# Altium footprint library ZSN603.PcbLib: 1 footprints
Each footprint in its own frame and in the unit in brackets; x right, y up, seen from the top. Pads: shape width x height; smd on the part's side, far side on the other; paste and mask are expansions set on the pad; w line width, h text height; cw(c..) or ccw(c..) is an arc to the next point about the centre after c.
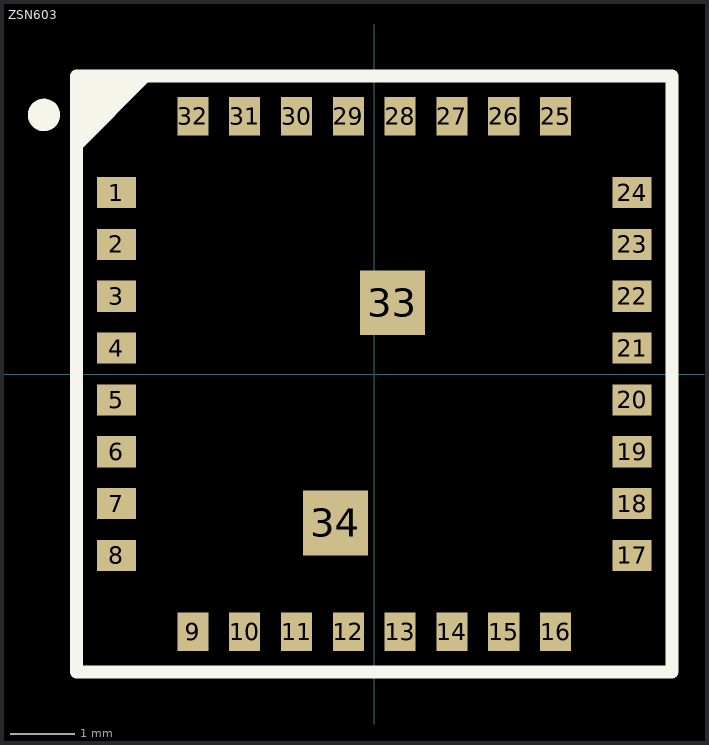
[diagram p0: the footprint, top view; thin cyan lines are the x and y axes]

## ZSN603 [mm]
height 1.11
pads (34):
  rect 0.6x0.48 smd mask+0.07: 1(-3.98,2.8) 2(-3.98,2) 3(-3.98,1.2) 4(-3.98,0.4) 5(-3.98,-0.4) 6(-3.98,-1.2) 7(-3.98,-2) 8(-3.98,-2.8) 17(3.98,-2.8) 18(3.98,-2) 19(3.98,-1.2) 20(3.98,-0.4) 21(3.98,0.4) 22(3.98,1.2) 23(3.98,2) 24(3.98,2.8)
  rect 0.48x0.6 smd mask+0.07: 9(-2.8,-3.98) 10(-2,-3.98) 11(-1.2,-3.98) 12(-0.4,-3.98) 13(0.4,-3.98) 14(1.2,-3.98) 15(2,-3.98) 16(2.8,-3.98) 25(2.8,3.98) 26(2,3.98) 27(1.2,3.98) 28(0.4,3.98) 29(-0.4,3.98) 30(-1.2,3.98) 31(-2,3.98) 32(-2.8,3.98)
  rect 1x1 smd mask+0.07: 33(0.28,1.1) 34(-0.6,-2.3)
Top Overlay:
  circle w0.25: c-5.1,4 r0.125
  region: -3.45,4.55 -4.55,3.45 -4.55,4.55
  lines w0.2: -4.6,-4.6 4.6,-4.6 4.6,4.6 -4.6,4.6 -4.6,-4.6
3D body: height 0.8, standoff 0, extent -4.55,-4.55 4.55,4.55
